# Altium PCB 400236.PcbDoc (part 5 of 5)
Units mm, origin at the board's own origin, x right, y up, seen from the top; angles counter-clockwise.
Board outline 136.53 x 63.5 mm, 4 copper layers (Top Layer, Mid-Layer 1, Mid-Layer 2, Bottom Layer), stack 1.49 mm thick; 344 components, 236 nets, 1364 pads, 1393 vias.
Unrouted connection lines stored in the file: 6.
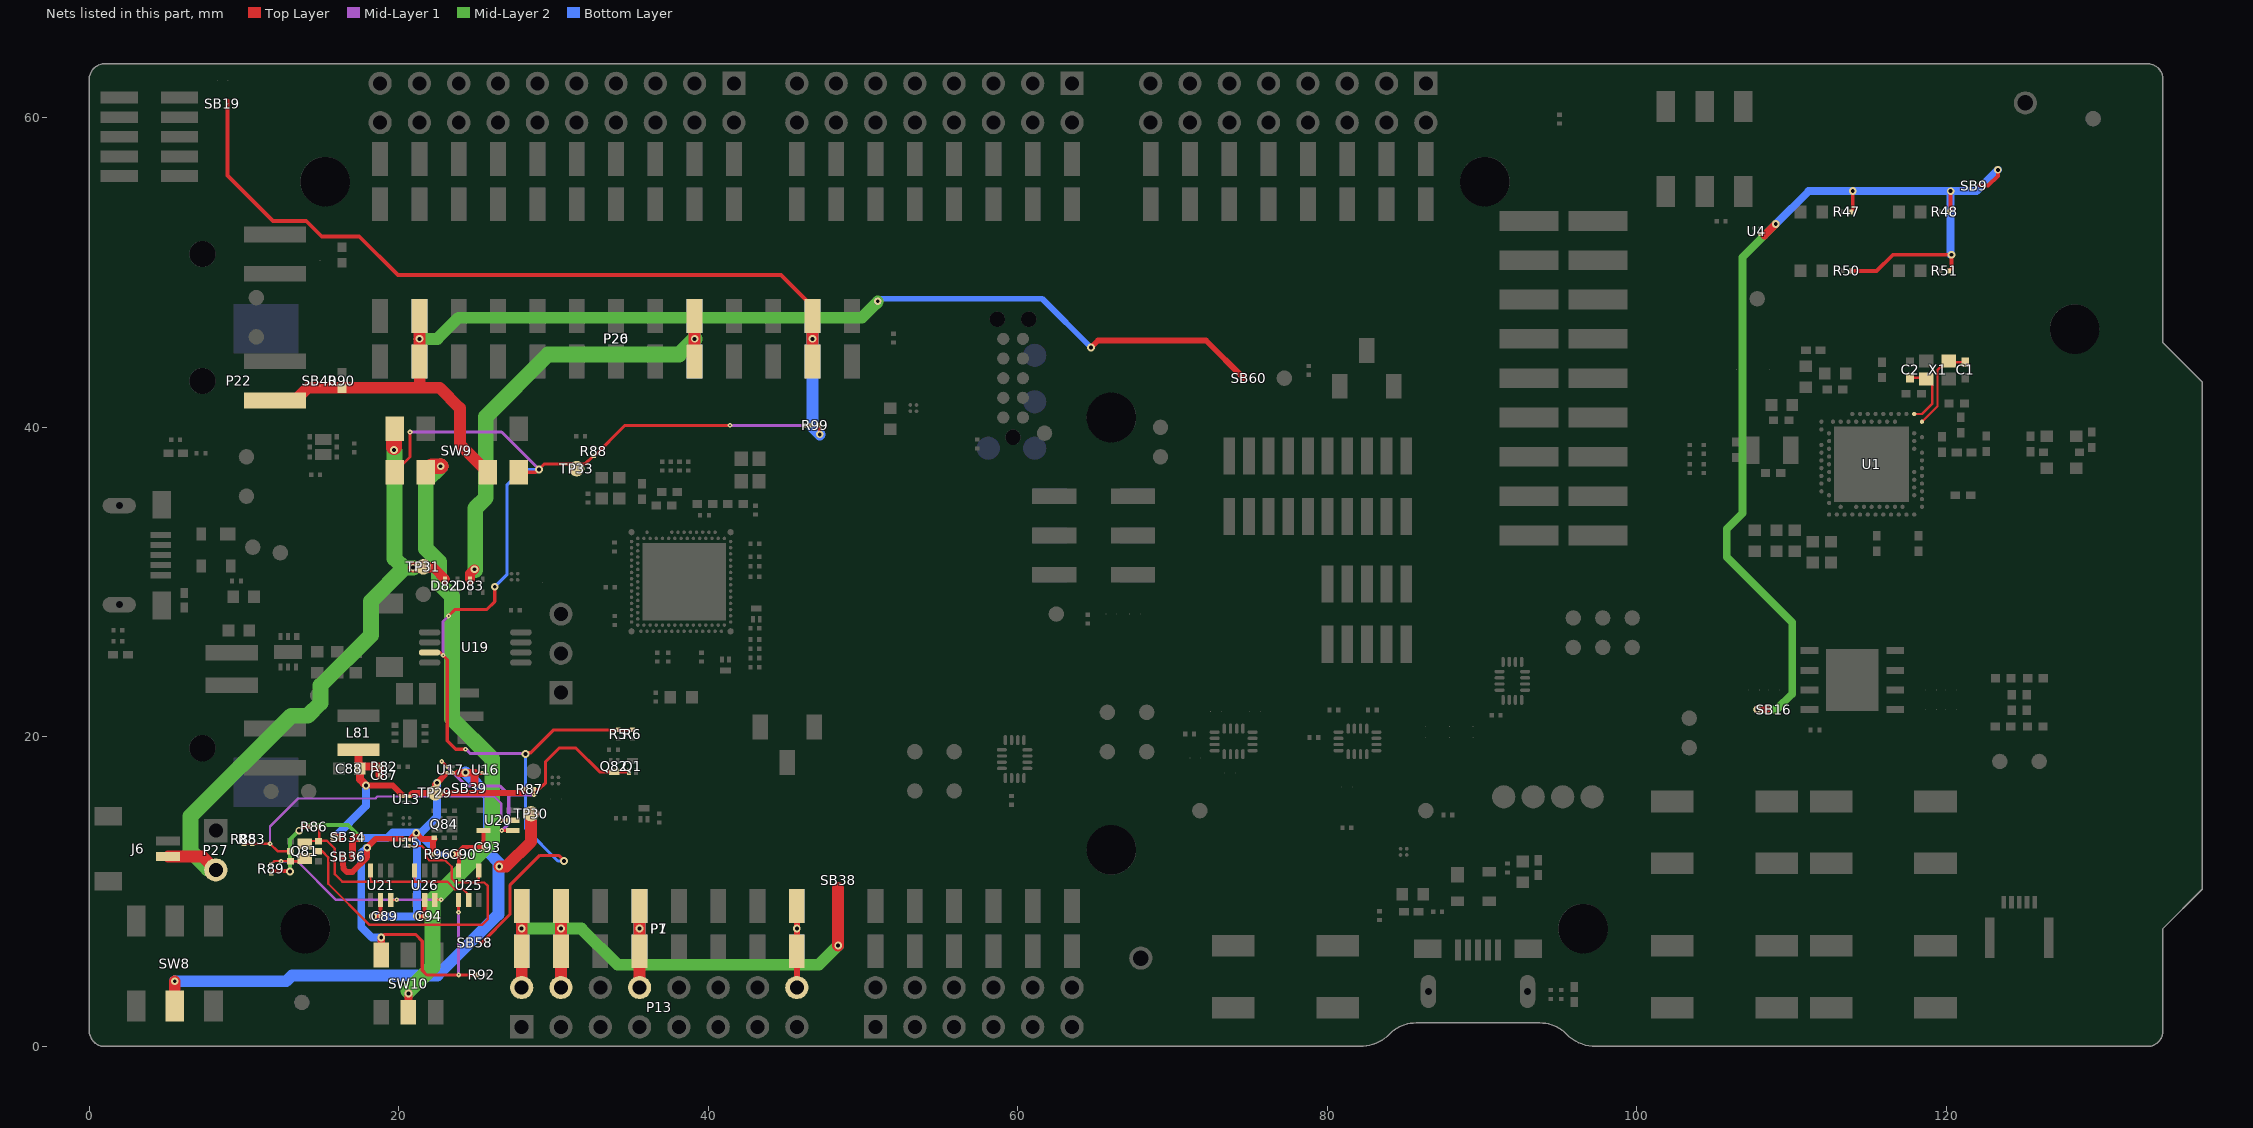
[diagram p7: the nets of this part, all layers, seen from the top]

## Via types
v1: diameter 0.5, hole 0.25, Top Layer to Bottom Layer, tented both sides, 1166 vias
v2: diameter 0.3, hole 0.1, Top Layer to Mid-Layer 1, tented top, 227 vias

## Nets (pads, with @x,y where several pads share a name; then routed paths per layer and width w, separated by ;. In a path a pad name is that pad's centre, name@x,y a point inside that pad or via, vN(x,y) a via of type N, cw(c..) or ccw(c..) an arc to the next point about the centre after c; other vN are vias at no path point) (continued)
VDD_NRF': P20.2 P22.2 P26.2 R90.1 SB40.2 SB60.2 SW9.3 | length 85.3
  Top Layer w0.381: v1(64.719,45.161) 65.176,45.618 72.154,45.618 SB60.2@74.592,43.18
  Top Layer w0.508: P20.2@21.336,44.255 v1(21.336,45.72) P20.2@21.336,47.185
  Top Layer w0.762: P22.2@11.811,41.73 13.284,41.73 14.115,42.561 21.361,42.561 ; P20.2@21.336,47.185 v1(21.336,45.72) P20.2@21.336,44.255 21.361,44.23 21.361,42.561 ; SW9.3@25.749,37.106 23.952,38.903 23.952,41.25 22.641,42.561 21.361,42.561
  Mid-Layer 2 w0.762: v1(21.336,45.72) 22.495,45.72 23.856,47.081 24.748,47.081 49.926,47.081 50.891,48.046 50.891,48.058 50.95,48.118 v1(50.95,48.15)
  Bottom Layer w0.381: v1(50.95,48.15) 50.982,48.15 51.143,48.311 61.57,48.311 v1(64.719,45.161)
  Bottom Layer w0.508: P26.2@21.336,44.255 v1(21.336,45.72) P26.2@21.336,47.185
VDD_NRF_SENSE: R5.1 R6.2 R88.1 R99.1 SB58.1 SW9.1 SW9.4 TP33.1 U19.3 | length 85.6
  Top Layer w0.203: SW9.1@19.749,37.106 20.726,38.084 v2(20.726,39.7) ; U19.3@21.993,25.456 22.677,25.456 v2(22.86,25.273) 23.129,25.004 23.129,19.747 23.673,19.202 v2(24.311,19.202) ; v2(23.216,27.813) 23.647,28.245 25.705,28.245 26.2,28.74 v1(26.2,29.705) ; SB58.1@25.255,6.706 25.356,6.706 27.178,8.528 27.178,10.408 29.117,12.347 30.325,12.347 v1(30.683,11.989) ; SW9.4@27.749,37.106 28.877,37.106 v1(29.058,37.287) 29.413,37.643 32.06,37.643 32.54,38.122 32.54,38.137 32.573,38.171 R88.1@32.588,38.171 ; v1(28.194,18.898) 28.272,18.975 28.525,18.975 30.01,20.46 R5.1@34.175,20.46 R6.2@35.1,20.46 ; R88.1@32.619,38.137 34.613,40.132 v2(41.402,40.132) ; v2(46.25,40.15) R99.1@46.615,40.15
  Mid-Layer 1 w0.203: v2(20.726,39.7) 26.645,39.7 v1(29.058,37.287) ; v2(22.86,25.273) 22.86,27.457 v2(23.216,27.813) ; v2(24.311,19.202) 24.351,19.202 24.634,18.919 28.173,18.919 v1(28.194,18.898) ; v2(41.402,40.132) 46.232,40.132 v2(46.25,40.15)
  Bottom Layer w0.203: v1(26.2,29.705) 27,30.505 27,36.297 27.991,37.287 v1(29.058,37.287) ; v1(28.194,18.898) 28.194,14.078 30.283,11.989 v1(30.683,11.989)
VDD_PER: R47.2 R48.2 R50.2 R51.2 SB9.2 SB16.1 U4.A1 | length 71.5
  Top Layer w0.25: U4.A1@107.95,52.476 108.235,52.476
  Top Layer w0.254: R50.2@113.844,50.107 115.487,50.107 116.535,51.156 v1(120.316,51.156) 120.316,50.269 120.169,50.122 R51.2@120.169,50.107 ; R47.2@113.844,53.917 113.844,53.932 113.94,54.028 v1(113.94,55.271) 113.94,54.443 ; R48.2@120.169,53.917 120.169,53.932 120.265,54.028 v1(120.265,55.264) ; 122.114,55.619 122.289,55.619 122.684,55.619 123.317,56.252 v1(123.317,56.642)
  Top Layer w0.381: v1(107.772,21.768) SB16.1@108.501,21.768
  Top Layer w0.508: 108.229,52.4 v1(108.966,53.137)
  Mid-Layer 2 w0.508: v1(107.772,21.768) 109.017,21.768 110.033,22.784 110.033,27.395 105.804,31.623 105.804,33.44 106.819,34.455 106.819,50.99 v1(108.966,53.137)
  Bottom Layer w0.508: v1(108.966,53.137) 111.093,55.264 v1(120.265,55.264) ; v1@120.265,51.156 v1(120.265,55.264) ; v1(123.317,56.642) 121.939,55.264 v1(120.265,55.264)
VEXT: R92.1 SB36.2 SW10.3 U15.A1 U25.1 | length 27.6
  Top Layer w0.203: v1(18.872,7.036) 19.078,7.241 21.08,7.241 21.514,6.807 21.514,4.928 21.819,4.623 v2(23.876,4.623) R92.1@25.064,4.623 ; SW10.3@18.875,5.914 SW10.3@18.875,6.251 ; v2(23.861,8.676) U25.1@23.861,9.464
  Top Layer w0.381: 16.397,12.265 16.397,11.912 16.402,11.832 16.403,11.824 16.425,11.493 16.643,11.275 17,11.275 17.958,12.233 17.958,12.878 18.504,13.424 U15.A1@20.231,13.424
  Top Layer w0.508: v1(18.872,7.036) 18.872,5.917 SW10.3@18.875,5.914
  Mid-Layer 1 w0.203: v2(23.861,8.676) 23.861,4.638 v2(23.876,4.623)
  Bottom Layer w0.508: v1(17.958,12.842) 17.922,12.842 17.577,12.497 17.577,7.722 18.263,7.036 v1(18.872,7.036)
VEXT_EN: Q81.5 U15.B2 U25.4 | length 23.7
  Top Layer w0.152: Q81.5@14.864,12.624 15.037,12.624 15.443,12.217 15.443,10.516 18.085,7.874 25.4,7.874 25.756,8.23 25.756,10.363 25.527,10.592 25.171,10.592 ; U15.B2@20.698,12.957 21.485,12.957 21.793,12.649 21.793,12.217 21.971,12.039 22.988,12.039 23.419,11.608 23.419,10.846 23.673,10.592 25.171,10.592 ; U25.4@25.161,11.364 25.161,10.602 25.171,10.592
VEXT_EN_INV: Q81.3 R89.2 U21.6 U26.6 | length 14.6
  Top Layer w0.152: R89.2@11.76,11.766 11.775,11.766 11.834,11.825 11.834,11.84 11.975,11.981 12.962,11.981 Q81.3@12.969,11.974 ; Q81.3@12.974,11.974 13.744,11.974 Q81.3@13.919,12.149 ; Q81.3@13.955,11.974 Q81.3@13.995,12.014 ; U21.6@19.471,9.464 19.853,9.464 v2(19.863,9.474) ; U26.6@22.316,9.464 22.326,9.474 v2(22.733,9.474)
  Mid-Layer 1 w0.152: v2(12.395,11.963) 13.462,11.963 15.951,9.474 v2(19.863,9.474) v2(22.733,9.474)
VIN: P1.8 P7.8 P13.16 | length 8.2
  Top Layer w0.381: P13.16@45.72,3.81 P1.8@45.72,6.155 v1(45.72,7.62) P1.8@45.72,9.085
  Bottom Layer w0.381: P7.8@45.72,6.155 v1(45.72,7.62) P7.8@45.72,9.085
VIN3-5V: D83.2 P20.9 P26.9 | length 32.4
  Top Layer w0.635: D83.2@24.613,30.186 24.613,30.556 v1(24.892,30.836)
  Top Layer w0.762: P20.9@39.116,44.255 v1(39.116,45.72) P20.9@39.116,47.185
  Mid-Layer 2 w1.016: v1@24.943,30.785 24.943,34.773 25.629,35.458 25.629,40.691 29.642,44.704 38.1,44.704 v1@39.111,45.714
  Bottom Layer w0.762: P26.9@39.116,44.255 v1(39.116,45.72) P26.9@39.116,47.185
VIO: P1.1 P1.2 P1.4 P7.1 P7.2 P7.4 P13.2 P13.4 P13.8 SB38.1 | length 54.1
  Top Layer w0.381: v1(35.56,7.62) P1.4@35.56,9.085
  Top Layer w0.762: P13.2@27.94,3.81 P1.1@27.94,6.155 P1.1@27.94,9.085 ; P13.4@30.48,3.81 v1(30.48,7.62) P1.2@30.48,9.085 ; P13.8@35.56,3.81 P1.4@35.56,9.085 ; v1(48.387,6.528) 48.387,10.236
  Mid-Layer 2 w0.762: v1(27.94,7.62) v1(30.48,7.62) 31.801,7.62 34.138,5.283 35.535,5.283 ; v1(35.56,7.62) 35.56,5.309 35.535,5.283 ; v1(48.387,6.528) 47.142,5.283 35.535,5.283
  Bottom Layer w0.762: P7.1@27.94,6.155 P7.1@27.94,9.085 ; P7.2@30.48,6.155 P7.2@30.48,9.085 ; P7.4@35.56,6.155 P7.4@35.56,9.085
VIO_REF: P20.12 P26.12 R99.2 SB19.2 | length 58.2
  Top Layer w0.2: R99.2@47.185,40.15 47.185,39.565 v1(47.2,39.55)
  Top Layer w0.25: 8.923,61.138 8.923,56.279 11.877,53.325 14.023,53.325 15.024,52.324 17.45,52.324 19.939,49.835 44.704,49.835 46.736,47.803 P20.12@46.736,47.185
  Top Layer w0.762: P20.12@46.736,44.255 v1(46.736,45.72) P20.12@46.736,47.185
  Bottom Layer w0.762: P26.12@46.736,47.185 v1(46.736,45.72) P26.12@46.736,44.255 46.736,40.014 v1(47.2,39.55)
VLI-ION: D82.2 J6.2 P27.2 SW9.5 TP31.1 | length 42.2
  Top Layer w0.635: v1(20.93,30.937) 22.235,30.937 D82.2@22.987,30.186
  Top Layer w0.762: J6.2@5.105,12.276 7.307,12.276 P27.2@8.179,11.405
  Top Layer w1.016: v1@19.685,38.735 19.685,39.842 SW9.5@19.749,39.906
  Mid-Layer 2 w1.016: P27.2@8.179,11.405 8.086,11.497 7.68,11.497 6.55,12.627 6.55,14.875 13.05,21.375 14.125,21.375 14.95,22.2 14.95,23.325 18.2,26.575 18.2,28.775 20.362,30.937 ; v1@19.725,38.492 19.725,31.532 20.32,30.937 20.362,30.937 ; v1(20.93,30.937) 20.362,30.937
  other v1: 19.685,38.532
VREG: C87.2 C88.2 L81.2 R82.2 SB34.2 U13.A1 | length 11.5
  Top Layer w0.381: v1(17.882,16.866) 19.609,16.866 U13.A1@20.231,16.243
  Top Layer w0.508: v1(15.843,13.509) 16.222,13.509 16.223,13.508 ; L81.2@17.399,19.093 17.399,18.049 C88.2@17.49,17.958 ; v1(17.882,16.866) 17.49,17.257 C88.2@17.49,17.958 ; C87.2@18.79,17.526 18.765,17.551 R82.2@18.765,18.085 17.617,18.085 C88.2@17.49,17.958
  Bottom Layer w0.508: v1(15.843,13.509) 17.882,15.548 v1(17.882,16.866)
VREG_EN: Q81.2 R83.2 R85.1 U20.2 | length 22
  Top Layer w0.152: R85.1@10.004,13.101 R83.2@10.538,13.101 v2(11.684,13.101) 12.161,12.624 Q81.2@12.969,12.624 ; v2(26.619,14.605) U20.2@27.366,14.605
  Mid-Layer 1 w0.152: v2(11.684,13.101) 11.684,14.209 13.499,16.024 18.489,16.024 18.615,16.15 26.166,16.15 26.619,15.697 v2(26.619,14.605)
VREG_EN_INV: Q81.6 R86.2 U21.3 U25.2 U26.3 | length 15.4
  Top Layer w0.152: Q81.6@13.919,13.099 14.094,13.274 Q81.6@14.864,13.274 ; R86.2@14.851,14.2 14.851,13.292 15.359,13.292 15.875,12.776 15.875,11.125 16.358,10.643 18.171,10.643 ; U21.3@18.171,11.364 18.171,10.643 ; U26.3@21.016,11.364 21.016,10.643 ; U25.2@24.511,9.804 24.155,10.16 23.622,10.16 23.139,10.643 21.016,10.643 ; 18.171,10.643 21.016,10.643
VSENSE_SW_OUT: SB39.1 SW8.2 TP30.1 U16.A2 U17.A1 | length 41.3
  Top Layer w0.25: U17.A1@23.517,17.682 23.876,17.682 ; 24.953,17.664 25.36,17.664 U16.A2@25.378,17.682
  Top Layer w0.508: 23.876,17.682 24.308,17.682 24.311,17.684 24.933,17.684 24.971,17.646 24.892,17.566 24.892,17
  Top Layer w0.762: SW8.2@5.528,2.609 v1(5.528,4.216) ; v1(26.492,11.633) 26.949,11.633 28.55,13.233 TP30.1@28.55,14.859
  Bottom Layer w0.762: v1(5.528,4.216) 12.727,4.216 13.106,4.596 22.503,4.596 26.441,8.534 26.441,11.909 25.829,12.521 25.829,16.182 v1(24.308,17.704)
VSRC_NRF: SW9.2 SW10.5 | length 40.6
  Top Layer w0.508: SW10.5@20.625,2.214 v1(20.625,3.429)
  Top Layer w1.016: SW9.2@21.749,37.106 22.133,37.49 v1(22.708,37.49)
  Mid-Layer 2 w1.016: v1@20.625,3.607 22.174,5.156 22.174,9.449 26.035,13.31 26.035,18.593 23.444,21.184 23.444,29.083 22.606,29.921 22.606,31.32 21.749,32.177 21.749,36.532 v1(22.708,37.49)
VSUPPLY: C89.2 C90.2 C93.2 C94.2 Q84.4 R86.1 R87.1 R89.1 R96.1 SB34.1 SB36.1 SB39.2 TP29.1 U13.A2 U15.A2 U17.A2 U20.5 U21.5 U25.5 U26.5 | length 48.9
  Top Layer w0.254: R89.1@11.76,11.196 11.775,11.196 11.908,11.328 v1@12.979,11.328 ; v1(13.564,13.945) 13.571,13.945 13.826,14.2 R86.1@14.265,14.2 ; v1(18.339,8.407) C89.2@18.816,8.407 18.816,9.458 U21.5@18.821,9.464 ; v1(21.184,8.407) C94.2@21.661,8.407 21.661,9.458 U26.5@21.666,9.464 ; U25.5@23.861,11.364 23.896,11.399 C90.2@23.896,12.421 23.896,12.62 24.154,12.878 C93.2@25.471,12.878 25.471,13.95 U20.5@25.466,13.955
  Top Layer w0.381: U15.A2@20.764,13.424 v1(21.128,13.787) 21.504,13.411 22.301,13.411 22.219,13.329 R96.1@22.219,12.471 ; U13.A2@20.777,16.256 20.912,16.391 22.352,16.391 22.352,16.916 v1(22.479,17.043) U17.A2@23.038,17.602 ; TP29.1@22.352,16.383 22.352,16.386 24.201,16.386 24.922,16.386 27.937,16.386 R87.1@28.163,16.612 ; v1(23.444,12.421) C90.2@23.896,12.421
  Top Layer w0.457: 17.022,12.265 17.022,12.618 17.022,13.182 17.022,13.184
  Top Layer w0.508: 17.085,13.469 17.191,13.469 17.544,13.469 v1(17.55,13.475)
  Mid-Layer 2 w0.254: v1(12.979,11.303) 12.979,13.36 v1(13.564,13.945) 13.919,14.3 16.725,14.3 v1(17.55,13.475)
  Bottom Layer w0.381: v1@21.295,13.675 22.55,12.421 v1(23.444,12.421)
  Bottom Layer w0.508: v1(17.55,13.475) 19.257,13.475 19.625,13.843 v1@21.128,13.843 ; v1(18.339,8.407) v1(21.184,8.407) 21.184,13.787 v1@21.128,13.843 ; v1(22.479,17.043) 22.479,14.859 21.463,13.843 v1@21.128,13.843
VSUPPLY_EN: Q1.1 Q82.3 R87.2 U17.B2 U20.1 | length 19.6
  Top Layer w0.152: v2(22.784,18.415) U17.B2@23.117,18.082
  Top Layer w0.203: v2(26.66,13.955) U20.1@27.366,13.955 ; v2(28.733,16.262) R87.2@28.733,16.612 29.058,16.612 29.489,17.043 29.489,18.415 30.362,19.288 31.437,19.288 32.975,17.75 Q82.3@33.925,17.75 Q1.1@34.875,17.75
  Mid-Layer 1 w0.203: v2(22.784,18.415) 24.359,16.84 26.518,16.84 27.096,16.262 ; v2(26.66,13.955) 27.102,14.397 27.102,16.256 27.096,16.262 ; v2(28.733,16.262) 27.096,16.262
XC1: C1.1 U1.B24 X1.1 | length 5.8
  Top Layer w0.152: U1.B24@118.414,40.367 119.414,41.367 119.414,43.717 119.909,44.213 C1.1@121.203,44.213
XC2: C2.1 U1.A23 X1.3 | length 4.3
  Top Layer w0.152: C2.1@117.647,43.213 118.625,43.213 X1.3@118.7,43.138 119.089,42.749 119.089,41.538 118.418,40.867 U1.A23@117.914,40.867
pads on no net: Fid1.0 Fid2.0 J2.4 J2.6@1.944,28.55 J2.6@1.944,34.95 J3.4 J3.6@86.529,3.557 J3.6@92.929,3.557 J4.0 J4.6 J4.7 J4.8 J4.9 J5.0 J5.1 J5.3 J5.5 J6.0 P18.7 P18.8 P19.7 P19.8 P19.9 P21.0 P22.0 P23.0 P25.7 P25.8 P25.11 P25.13 SW8.1 U2. U2.A1 U2.A17 U2.A21 U2.A31 U2.AB2 U2.AD2 U2.AE1 U2.AE31 U2.AF2 U2.AG31 U2.AH2 U2.AJ1 U2.AK2 U2.AK4 U2.AK6 U2.AK8 U2.AK10 U2.AK12 U2.AK14 U2.AK16 U2.AK18 U2.AK20 U2.AL1 U2.AL13 U2.AL15 U2.AL21 U2.AL23 U2.AL31 U2.B10 U2.B14 U2.D2 U2.F2 U2.J1 U2.K2 U2.M2 U2.P2 U2.R31 U2.T2 U2.V2 U2.Y2 U5.1 U5.9 U5.13 U6.1 U6.5 U6.9 U6.13 U7.7 U7.11 U8.11 U8.12 U8.13

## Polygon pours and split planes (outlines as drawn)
VDD on Mid-Layer 2 "Mid_Layer_2-VDD" (solid, remove dead copper, pour order 10): -3.81,-3.81 -3.81,68.58 138.43,68.58 138.43,-3.81
VDD_IMCU on Mid-Layer 2 "Mid_Layer_2-VDD_IMCU" (solid, remove dead copper, pour order 8): 33.025,35.987 33.025,25.093 43.937,25.093 43.937,35.987
GND on Bottom Layer "Bottom_Layer-GND" (solid, remove dead copper, pour order 6): -3.81,-3.81 -3.81,68.58 138.43,68.58 138.43,-3.81
GND on Mid-Layer 1 "Mid_Layer_1-GND" (solid, remove dead copper, pour order 7): -3.81,-3.81 -3.81,68.58 138.43,68.58 138.43,-3.81
GND on Top Layer "Top_Layer-GND" (solid, remove dead copper, pour order 12): -3.81,-3.81 -3.81,68.58 138.43,68.58 138.43,-3.81

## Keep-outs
Top Layer:
  lines w0.152: 90.89,53.591 cw(c90.17,55.88) 91.893,54.209
Mid-Layer 1:
  circle w0.152: c90.17,55.88 r2.4
Mid-Layer 2:
  circle w0.152: c90.17,55.88 r2.4
Bottom Layer:
  circle w0.152: c90.17,55.88 r2.4
Keep-Out Layer:
  circle w0.152: c13.97,7.62 r2.4
  circle w0.152: c66.04,12.7 r2.4
  circle w0.152: c128.27,46.355 r2.4
  circle w0.152: c15.24,55.88 r2.4
  circle w0.152: c66.04,40.64 r2.4
  circle w0.152: c96.52,7.62 r2.4
  circle w0.1: c13.967,0 r0.3
  circle w0.1: c15.067,0 r0.3
  circle w0.1: c16.167,0 r0.3
  circle w0.1: c123.987,0 r0.3
  circle w0.1: c122.887,0 r0.3
  circle w0.1: c121.787,0 r0.3
  circle w0.1: c136.526,42.025 r0.3
  circle w0.1: c136.526,40.926 r0.3
  circle w0.1: c136.526,39.826 r0.3
  circle w0.1: c121.787,63.5 r0.3
  circle w0.1: c122.887,63.5 r0.3
  circle w0.1: c123.987,63.5 r0.3
  circle w0.1: c13.967,63.5 r0.3
  circle w0.1: c15.067,63.5 r0.3
  circle w0.1: c16.167,63.5 r0.3
  circle w0.1: c0,48.692 r0.3
  circle w0.1: c0,49.792 r0.3
  circle w0.1: c0,50.891 r0.3
  circle w0.1: c0,17.705 r0.3
  circle w0.1: c0,18.804 r0.3
  circle w0.1: c0,19.904 r0.3

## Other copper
Top Layer:
  rectangle net V5V: 13.231,24.103 13.866,24.738
  rectangle net ANT: 134.92,20.343 136.19,21.105
  pour cut-out: 17.625,25.8 18.65,25.8 18.775,25.675 18.775,25 18.375,24.6 17.725,24.6 17.625,24.7 17.625,24.875
  pour cut-out: 90.658,5.004 90.658,7.315 96.62,7.315 96.62,5.004
  pour cut-out: 91.161,32.131 91.161,33.401 89.891,33.401 89.891,32.131
  pour cut-out: 107.164,32.217 107.164,33.617 110.834,33.617 110.834,32.217
  pour cut-out: 110.664,31.367 110.664,32.867 113.164,32.867 113.164,31.367
  pour cut-out: 115.414,36.867 115.414,38.367 117.914,38.367 117.914,36.867
  pour cut-out: 117.737,33.63 116.676,34.691 118.444,36.458 119.505,35.398
  pour cut-out: 60.528,30.937 68.073,30.937 68.071,32.715 60.528,32.715
  pour cut-out: 129.92,-1.27 136.786,-1.27 136.748,45.415 129.925,45.415
  pour cut-out: -0.229,28.204 2.824,28.204 2.818,35.281 -0.228,35.281
  pour cut-out: 28.981,25.603 28.981,26.873 27.711,26.873 27.711,25.603
  pour cut-out: 118.567,26.975 117.297,26.975 117.297,25.705 118.567,25.705
  pour cut-out: 11.252,51.765 9.982,51.765 9.982,50.495 11.252,50.495
  pour cut-out: 86.385,35.687 85.115,35.687 85.115,34.417 86.385,34.417
  pour cut-out: 60.757,53.086 48.387,53.086 48.387,51.816 60.757,51.816
  pour cut-out: 107.163,43.256 107.163,44.526 105.054,44.526 105.054,43.256
  pour cut-out: 22.149,1.168 22.149,2.438 20.879,2.438 20.879,1.168
  pour cut-out: 20.447,5.715 20.447,6.985 19.177,6.985 19.177,5.715
  pour cut-out: 20.218,1.143 20.218,3.264 18.948,3.264 18.948,1.143
  pour cut-out: 11.252,43.635 9.982,43.635 9.982,42.365 11.252,42.365
  pour cut-out: 118.496,37.293 121.239,37.293 121.239,39.142 120.439,39.142 120.439,40.188 118.496,40.188
Mid-Layer 1:
  pour cut-out: 110.28,27.254 110.28,21.336 106.28,21.336 106.28,27.254
  pour cut-out: 121.71,25.984 121.71,20.066 117.71,20.066 117.71,25.984
  pour cut-out: 49.126,39.244 49.126,41.556 51.5,41.556 51.5,39.244
  pour cut-out: 110.28,18.44 107.467,18.44 107.467,25.333 110.28,25.333
  pour cut-out: 28.315,29.25 28.315,31.318 30.325,31.318 30.325,29.25
  pour cut-out: 92.078,58.763 92.078,61.074 95.377,61.074 95.377,58.763
  pour cut-out: 85.782,11.379 85.782,13.691 88.157,13.691 88.157,11.379
  pour cut-out: 129.92,-1.27 136.786,-1.27 136.748,45.415 129.925,45.415
  pour cut-out: 104.44,46.723 110.357,46.723 110.357,42.723 104.44,42.723
  pour cut-out: 15.45,11.557 15.45,14.529 17.824,14.529 17.824,11.557
  pour cut-out: 23.4,15.494 23.4,17.805 25.774,17.805 25.774,15.494
  pour cut-out: 56.725,19.202 56.725,21.514 59.099,21.514 59.099,19.202
  pour cut-out: 56.598,17.094 56.598,19.406 58.972,19.406 58.972,17.094
  pour cut-out: 60.618,17.843 60.618,20.155 62.992,20.155 62.992,17.843
  pour cut-out: 59.969,14.973 59.969,17.285 62.344,17.285 62.344,14.973
  pour cut-out: 64.878,26.695 64.878,29.007 68.656,29.007 68.656,26.695
  pour cut-out: 120.612,48.831 120.612,57.137 122.987,57.137 122.987,48.831
  pour cut-out: 7.449,59.95 7.449,63.449 9.823,63.449 9.823,59.95
  pour cut-out: 70.263,17.45 70.263,19.761 72.637,19.761 72.637,17.45
  pour cut-out: 71.438,20.587 71.438,22.898 73.812,22.898 73.812,20.587
  pour cut-out: 74.175,20.512 74.175,22.823 76.549,22.823 76.549,20.512
  pour cut-out: 73.369,16.612 73.369,18.923 75.744,18.923 75.744,16.612
  pour cut-out: 28.448,14.884 28.448,17.196 31.747,17.196 31.747,14.884
  pour cut-out: 80.042,13.995 80.042,18.161 82.416,18.161 82.416,13.995
  pour cut-out: 84.979,19.177 84.979,21.488 90.941,21.488 90.941,19.177
  pour cut-out: 13.678,49.898 13.678,52.21 16.053,52.21 16.053,49.898
  pour cut-out: 13.704,41.87 13.704,44.181 16.078,44.181 16.078,41.87
  pour cut-out: 47.232,9.614 47.232,11.925 49.606,11.925 49.606,9.614
  pour cut-out: 23.654,5.486 23.654,7.798 26.028,7.798 26.028,5.486
  pour cut-out: 73.641,41.986 73.641,44.298 76.016,44.298 76.016,41.986
  pour cut-out: 73.667,40.03 73.667,42.342 76.041,42.342 76.041,40.03
  pour cut-out: 131.445,36.392 119.918,36.392 119.918,40.392 131.445,40.392
Mid-Layer 2:
  pour cut-out: 27.742,32.85 26.8,32.85 26.8,32.925 27.75,32.925
  pour cut-out: 129.92,-1.27 136.786,-1.27 136.748,45.415 129.925,45.415
  pour cut-out: 131.445,36.392 119.918,36.392 119.918,40.392 131.445,40.392
Bottom Layer:
  pour cut-out: 129.92,-1.27 136.786,-1.27 136.748,45.415 129.925,45.415

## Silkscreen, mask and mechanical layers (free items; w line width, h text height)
Top Overlay:
  drawing of 85 lines, arcs and shapes, not listed
  text "nRF ONLY" at 97.765,62.052 h1.65
  text "DEFAULT" at 104.877,62.052 h1.65
  text "GND" at 12.225,61.7 h1.8
  text "GND" at 91.389,61.709 h1.8
  text ".PCBNumber" at 116.028,61.468 h2
  text ".PCBRevision" at 116.093,60.165 h1.5
  text "GND" at 123.469,58.471 h1.8
  text "LED1" at 109.622,54.654 h2.03
  text "LED2" at 115.82,54.654 h2.03
  text "Debug out" at 0.406,54.127 h1.78
  text "P0.11" at 87.757,52.781 h1.65
  text "P0.12" at 99.568,52.781 h1.65
  text "LED3" at 109.495,50.869 h2.03
  text "LED4" at 115.845,50.869 h2.03
  text "VDD_HV" at 1.016,50.775 h1.4
  text "P0.13" at 87.757,50.241 h1.65
  text "P0.14" at 99.568,50.241 h1.65
  text "P0.27" at 19.304,49.661 h1.65 r90
  text "P0.26" at 21.844,49.661 h1.65 r90
  text "P0.02" at 24.384,49.661 h1.65 r90
  text "GND" at 26.924,49.661 h1.65 r90
  text "P1.15" at 29.464,49.661 h1.65 r90
  text "P1.14" at 32.004,49.661 h1.65 r90
  text "P1.13" at 34.544,49.661 h1.65 r90
  text "P1.12" at 37.084,49.661 h1.65 r90
  text "P1.11" at 39.624,49.661 h1.65 r90
  text "P1.10" at 42.164,49.661 h1.65 r90
  text "P1.08" at 46.228,49.661 h1.65 r90
  text "P1.07" at 48.768,49.661 h1.65 r90
  text "P1.06" at 51.308,49.661 h1.65 r90
  text "P1.05" at 53.848,49.661 h1.65 r90
  text "P1.04" at 56.388,49.661 h1.65 r90
  text "P1.03" at 58.928,49.661 h1.65 r90
  text "P1.02" at 61.468,49.661 h1.65 r90
  text "P0.10" at 69.088,49.661 h1.65 r90
  text "P0.09" at 71.628,49.661 h1.65 r90
  text "P0.08" at 74.168,49.661 h1.65 r90
  text "P0.07" at 76.708,49.661 h1.65 r90
  text "P0.06" at 79.248,49.661 h1.65 r90
  text "P0.05" at 81.788,49.661 h1.65 r90
  text "P0.01" at 84.328,49.661 h1.65 r90
  text "P0.00" at 86.868,49.661 h1.65 r90
  text "P0.15" at 87.757,47.701 h1.65
  text "P0.16" at 99.568,47.701 h1.65
  text "nRF current" at 0.483,47.193 h1.78
  text "measurement" at 0.483,45.898 h1.78
  text "For evaluation only; / not FCC approved for resale." at 133.655,45.575 h1.52 r90
  text "Alt." at 79.756,45.339 h1.65
  text "Def." at 83.439,45.339 h1.65
  text "P0.17" at 87.757,45.161 h1.65
  text "P0.18" at 99.568,45.161 h1.65
  text "GPIO" at 102.997,44.958 h1.4
  text "XTAL" at 102.997,43.688 h1.4
  text "P0.19" at 87.757,42.621 h1.65
  text "P0.20" at 99.568,42.621 h1.65
  text "VDD" at 1.016,42.57 h1.4
  text "VIO / REF" at 47.705,40.946 h1.14 r90
  text "SWD / SEL" at 24.65,40.775 h1.14 r90
  text "VDD / nRF" at 19.761,40.755 h1.14 r90
  text "VDD / nRF'" at 22.301,40.755 h1.14 r90
  text "SWO" at 31.825,40.65 h1.14 r90
  text "(ARDUINO D0) P1.01" at 64.059,40.552 h1.65 r90
  text "SWD / IO" at 27.508,40.527 h1.14 r90
  text "SWD / CLK" at 30.048,40.527 h1.14 r90
  text "TRACE" at 80.391,40.513 h1.65
  text "RESET" at 34.4,40.35 h1.14 r90
  text "P0.21" at 87.757,40.081 h1.65
  text "P0.22" at 99.568,40.081 h1.65
  text "VIN / 3-5V" at 40.1,39.85 h1.14 r90
  text "VDD / nRF_HV" at 42.625,38.975 h1.14 r90
  text "VDD / nRF_HV'" at 45.161,38.803 h1.14 r90
  text "P0.23" at 87.757,37.541 h1.65
  text "P0.24" at 99.568,37.541 h1.65
  text "IMCU USB" at 0.381,36.195 h2.29
  text "P1.14" at 57.889,35.082 h1.52
  text "5V" at 69.248,35.031 h1.52
  text "P0.25" at 87.757,35.001 h1.65
  text "P1.00" at 99.568,35.001 h1.65
  text "Li-Po   VDD   USB" at 18.313,34.95 h1.65
  text "nRF power source" at 17.12,33.299 h2.03
  text "P1.13" at 69.248,32.567 h1.52
  text "P1.15" at 57.918,32.542 h1.52
  text "P1.09" at 87.757,32.461 h1.65
  text "GND" at 99.568,32.461 h1.65
  text "DETECT" at 69.248,30.024 h1.52
  text "RESET" at 56.955,30.002 h1.52
  text "Debug in" at 79.052,23.3 h2
  text "SB20-22" at 106.934,22.225 h1.52 r90
  text "SB10-12" at 110.465,22.225 h1.52 r90
  text "External / supply" at -1.5,21.925 h1.78
  text "FLOW  / CONTROL" at 41.881,21.589 h1.65
  text "SB13-15" at 118.364,21.463 h1.52 r90
  text "SB23-25" at 121.92,21.463 h1.52 r90
  text "-" at 14.007,19.854 h3
  text "VCOM" at 37.05,18.825 h1.65
  text "BUTTON 1" at 102.594,17.19 h1.78
  text "BUTTON 2" at 112.641,17.19 h1.78
  text "+" at 13.737,17.065 h3
  text "ON" at 42.2,16.625 h1.65
  text "OFF" at 45.9,16.625 h1.65
  text "Li-po" at 2.825,15.425 h1.78
  text "-" at 5.487,13.582 h3
  text "N.C." at 46.253,10.465 h1.65 r90
  text "VDD" at 28.365,10.462 h1.65 r90
  text "VDD" at 30.905,10.462 h1.65 r90
  text "RESET" at 33.445,10.462 h1.65 r90
  text "VDD" at 35.985,10.462 h1.65 r90
  text "5V" at 38.525,10.462 h1.65 r90
  text "GND" at 41.065,10.462 h1.65 r90
  text "GND" at 43.605,10.462 h1.65 r90
  text "P0.03 (A0)" at 51.225,10.462 h1.65 r90
  text "P0.04" at 53.765,10.462 h1.65 r90
  text "P0.28" at 56.305,10.462 h1.65 r90
  text "P0.29" at 58.845,10.462 h1.65 r90
  text "P0.30" at 61.385,10.462 h1.65 r90
  text "P0.31" at 63.925,10.462 h1.65 r90
  text "+" at 5.216,10.332 h3
  text "NFC" at 123.123,9.926 h2.29
  text "BUTTON 4" at 112.691,8.011 h1.78
  text "BUTTON 3" at 102.518,8 h1.78
  text "RESET" at 75.31,7.871 h1.78
  text "nRF52840 USB" at 84.861,7.087 h1.78
  text "VEXT   nRF" at 16.662,6.807 h1.78
  text "GND" at 69.139,5.182 h1.8
  text "Power" at 11.506,3.2 h2.03 r90
  text "GND" at 68.402,0.761 h1.8
  text ".ProductName" at 132.669,0.755 h3 r90
  text "ON" at 2.911,0.229 h1.78
  text "OFF" at 5.655,0.229 h1.78
  text "OFF" at 18.009,0.203 h1.78
  text "ON" at 21.438,0.203 h1.78
Bottom Overlay:
  drawing of 1286 lines, arcs and shapes, not listed
  text "J-Link" at 10.033,62.614 h1.45 r90
  text "www.segger.com" at 11.184,62.532 h1.68 r90
  text "TM" at 9.611,59.144 h0.94 r90
  text "S" at 8.174,58.931 h1.35 r90
  text "E" at 8.174,58.041 h1.35 r90
  text "Technology" at 10.033,57.861 h1.45 r90
  text "G" at 8.174,57.257 h1.35 r90
  text "G" at 8.174,56.266 h1.35 r90
  text "E" at 8.174,55.242 h1.35 r90
  text "R" at 8.174,54.407 h1.35 r90
  text "P0.27" at 19.228,53.111 h1.52 r90
  text "P0.26" at 21.768,53.111 h1.52 r90
  text "P0.02" at 24.308,53.111 h1.52 r90
  text "GND" at 26.849,53.111 h1.52 r90
  text "P1.15" at 29.388,53.111 h1.52 r90
  text "P1.14" at 31.928,53.111 h1.52 r90
  text "P1.13" at 34.468,53.111 h1.52 r90
  text "P1.12" at 37.008,53.111 h1.52 r90
  text "P1.11" at 39.548,53.111 h1.52 r90
  text "P1.10" at 42.088,53.111 h1.52 r90
  text "P1.08" at 46.152,53.111 h1.52 r90
  text "P1.07" at 48.693,53.111 h1.52 r90
  text "P1.06 (D5)" at 51.233,53.111 h1.52 r90
  text "P1.05 (D4)" at 53.773,53.111 h1.52 r90
  text "P1.04 (D3)" at 56.313,53.111 h1.52 r90
  text "P1.03 (D2)" at 58.853,53.111 h1.52 r90
  text "P1.02 (D1)" at 61.393,53.111 h1.52 r90
  text "P1.01 (ARDUINO D0)" at 63.933,53.111 h1.52 r90
  text "P0.10" at 69.038,53.111 h1.52 r90
  text "P0.09" at 71.578,53.111 h1.52 r90
  text "P0.08" at 74.118,53.111 h1.52 r90
  text "P0.07" at 76.658,53.111 h1.52 r90
  text "P0.06" at 79.198,53.111 h1.52 r90
  text "P0.05" at 81.738,53.111 h1.52 r90
  text "P0.01" at 84.278,53.111 h1.52 r90
  text "P0.00" at 86.793,53.111 h1.52 r90
  text "(SCL)" at 20.346,52.07 h1.52 r90
  text "(SDA)" at 22.886,52.07 h1.52 r90
  text "(AREF)" at 25.426,52.07 h1.52 r90
  text "(D13)" at 30.506,52.07 h1.52 r90
  text "(D12)" at 33.046,52.07 h1.52 r90
  text "(D11)" at 35.586,52.07 h1.52 r90
  text "(D10)" at 38.126,52.07 h1.52 r90
  text "(D9)" at 40.666,52.07 h1.52 r90
  text "(D8)" at 43.206,52.07 h1.52 r90
  text "(D7)" at 47.27,52.07 h1.52 r90
  text "(D6)" at 49.81,52.07 h1.52 r90
  text "GPIO" at 76.911,48.701 h1.99 r90
  text "P0.00" at 80.747,48.441 h1.65 r90
  text "P0.01" at 86.131,48.441 h1.65 r90
  text "P0.11" at 90.17,48.441 h1.65 r90
  text "P0.12" at 92.862,48.441 h1.65 r90
  text "P0.24" at 95.555,48.441 h1.65 r90
  text "P0.25" at 98.247,48.441 h1.65 r90
  text "P0.13" at 100.94,48.441 h1.65 r90
  text "P0.14" at 103.632,48.441 h1.65 r90
  text "P0.15" at 106.324,48.441 h1.65 r90
  text "P0.16" at 109.017,48.441 h1.65 r90
  text "P0.17" at 111.713,48.459 h1.65 r90
  text "P0.19" at 114.405,48.459 h1.65 r90
  text "P0.20" at 117.098,48.459 h1.65 r90
  text "P0.21" at 119.79,48.459 h1.65 r90
  text "P0.22" at 122.483,48.459 h1.65 r90
  text "P0.23" at 125.175,48.459 h1.65 r90
  text "Function" at 76.9,42.875 h1.99 r90
  text "Button 1" at 90.12,42.415 h1.65 r90
  text "Button 2" at 92.812,42.415 h1.65 r90
  text "Button 3" at 95.505,42.415 h1.65 r90
  text "Button 4" at 98.197,42.415 h1.65 r90
  text "GPIO" at 27.3,41.775 h1.99 r90
  text "LED 1" at 100.915,41.622 h1.65 r90
  text "LED 2" at 103.607,41.622 h1.65 r90
  text "LED 3" at 106.299,41.622 h1.65 r90
  text "LED 4" at 108.992,41.622 h1.65 r90
  text "P0.05" at 29.82,41.583 h1.65 r90
  text "P0.06" at 32.512,41.583 h1.65 r90
  text "P0.07" at 35.204,41.583 h1.65 r90
  text "P0.08" at 37.897,41.583 h1.65 r90
  text "P0.18" at 40.589,41.583 h1.65 r90
  text "P1.00" at 43.282,41.583 h1.65 r90
  text "P0.09" at 52.222,41.583 h1.65 r90
  text "P0.10" at 56.794,41.583 h1.65 r90
  text "DIO0" at 117.098,41.5 h1.65 r90
  text "DIO1" at 119.79,41.5 h1.65 r90
  text "DIO2" at 122.483,41.5 h1.65 r90
  text "DIO3" at 125.175,41.5 h1.65 r90
  text "CLK" at 114.405,41.319 h1.65 r90
  text "XL2" at 86.131,41.111 h1.65 r90
  text "XL1" at 80.747,41.015 h1.65 r90
  text "CS" at 111.713,40.711 h1.65 r90
  text "SWDCLK" at 48.666,39.218 h1.65 r90
  text "SWDIO" at 45.925,38.7 h1.65 r90
  text "Function" at 27.3,36.025 h1.99 r90
  text "SB13/23" at 111.713,35.248 h1.65 r90
  text "SB11/21" at 114.405,35.248 h1.65 r90
  text "SB12/22" at 117.098,35.248 h1.65 r90
  text "SB14/24" at 119.79,35.248 h1.65 r90
  text "SB15/25" at 122.483,35.248 h1.65 r90
  text "SB10/20" at 125.175,35.248 h1.65 r90
  text "RESET" at 40.513,34.804 h1.65 r90
  text "NFC2" at 56.82,34.816 h1.65 r90
  text "NFC1" at 52.248,34.72 h1.65 r90
  text "SB2" at 79.4,34.671 h1.65 r90
  text "SB4" at 82.093,34.671 h1.65 r90
  text "SB1" at 84.785,34.671 h1.65 r90
  text "SB3" at 87.478,34.671 h1.65 r90
  text "SB5" at 100.94,34.671 h1.65 r90
  text "SB6" at 103.632,34.671 h1.65 r90
  text "SB7" at 106.324,34.671 h1.65 r90
  text "SB8" at 109.017,34.671 h1.65 r90
  text "SWO" at 43.231,34.573 h1.65 r90
  text "TXD" at 32.462,34.249 h1.65 r90
  text "RXD" at 37.846,34.259 h1.65 r90
  text "Short" at 76.911,34.155 h1.99 r90
  text "CTS" at 35.154,34.125 h1.65 r90
  text "RTS" at 29.769,34.044 h1.65 r90
  text "HW" at 27.73,28.448 h1.99 r90
  text "GPIO" at 85.083,27.927 h1.52 r90
  text "GPIO" at 120.015,27.927 h1.52 r90
  text "GPIO" at 34.773,27.813 h1.52 r90
  text "IMCU" at 43.334,27.812 h1.52 r90
  text "GPIO" at 57.93,26.381 h1.52 r90
  text "HW" at 76.911,25.519 h1.99 r90
  text "N.C" at 54.864,25.4 h1.27 r90
  text "SB2x" at 115.443,25.057 h1.27 r90
  text "SB1x" at 117.729,25.057 h1.27 r90
  text "PIN" at 50.883,24.171 h1.52 r90
  text "MEM" at 120.019,23.271 h1.52 r90
  text "VDD" at 101.803,23.126 h1.52 r90
  text "PIN" at 80.574,22.364 h1.52 r90
  text "PIN" at 115.57,22.364 h1.52 r90
  text "0R" at 57.658,22.225 h1.27 r90
  text "IF OFF" at 38.735,21.209 h1.52 r90
  text "NFC" at 53.957,21.224 h1.52 r90
  text "Button 1" at 106.324,18.061 h1.65 r90
  text "Button 2" at 108.9,18.061 h1.65 r90
  text "Function" at 103.775,18.05 h1.99 r90
  text "Function" at 116.916,17.284 h1.52 r90
  text "Default" at 124.474,17.183 h1.52 r90
  text "CTS" at 111.709,16.429 h1.65 r90
  text "P0.03 (A0)" at 51.181,16.393 h1.52 r90
  text "P0.30 (A4)" at 61.335,16.35 h1.52 r90
  text "P0.28 (A2)" at 56.261,16.229 h1.52 r90
  text "P0.29 (A3)" at 58.801,16.215 h1.52 r90
  text "P0.04 (A1)" at 53.721,16.083 h1.52 r90
  text "P0.31 (A5)" at 63.881,15.969 h1.52 r90
  text "RESET" at 33.447,13.808 h1.52 r90
  text "GND" at 41.067,13.139 h1.52 r90
  text "GND" at 43.53,13.139 h1.52 r90
  text "VDD" at 28.373,12.977 h1.52 r90
  text "VDD" at 30.913,12.977 h1.52 r90
  text "VDD" at 35.993,12.977 h1.52 r90
  text "N.C." at 46.197,12.665 h1.52 r90
  text "5V" at 38.558,11.889 h1.52 r90
  text "HW" at 114.249,11.676 h1.99 r90
  text "P0.11" at 106.224,10.079 h1.65 r90
  text "P0.12" at 108.917,10.079 h1.65 r90
  text "P0.07" at 111.609,10.079 h1.65 r90
  text "Def." at 103.835,9.957 h1.99 r90
  text "Alternative" at 124.46,9.055 h1.52 r90
  text "Pb" at 10.019,9.036 h3.05 r90
  text "TRACE / SW" at 121.234,8.648 h1.52 r90
  text "P1.07" at 106.224,5.301 h1.65 r90
  text "P1.08" at 108.917,5.301 h1.65 r90
  text "P0.04" at 111.609,5.301 h1.65 r90
  text "Alt." at 103.835,4.691 h1.99 r90
Board Outline:
  the board outline again, w0.254
Top Assembly:
  drawing of 47 lines, arcs and shapes, not listed
Bottom Assembly:
  drawing of 47 lines, arcs and shapes, not listed
Top Impedance:
  lines w0.138: 4.619,31.75 6.34,31.75 cw(c6.34,31.242) 6.699,31.601 7.244,31.055 7.244,31.062 7.754,31.571 ; 4.619,32.398 6.34,32.398 ccw(c6.34,32.906) 6.699,32.546 7.234,33.082 ; 7.244,33.099 7.248,33.095 7.754,32.59 ccw(c8.552,33.388) 8.552,32.259 11.506,32.259 ccw(c11.506,32.571) 11.727,32.35 11.811,32.434 cw(c12.344,31.901) 12.344,32.655 cw(c12.344,31.897) 12.88,32.433 12.964,32.349 ccw(c13.183,32.568) 13.163,32.259 ccw(c13.153,32.935) 13.631,32.457 14.84,33.666 ; 14.837,33.669 cw(c16.073,32.433) 16.063,34.181 ; 35.439,32.827 35.439,33.303 ; 35.839,32.827 35.839,32.877 35.714,33.002 35.714,33.379 ; 89.086,5.985 89.086,8.495 ccw(c88.578,8.495) 88.938,8.855 88.402,9.39 88.912,9.899 ccw(c88.114,10.697) 89.242,10.697 89.242,12.23 cw(c91.338,12.23) 91.338,14.326 ccw(c91.338,16.411) 92.813,14.936 94.183,16.307 ; 89.734,5.983 89.734,8.495 cw(c90.242,8.495) 89.883,8.855 ; 89.883,8.854 90.429,9.4 ; 90.44,9.39 89.931,9.899 cw(c90.729,10.697) 89.6,10.697 89.6,12.232 cw(c91.338,12.232) 91.338,13.97 ccw(c91.338,16.418) 93.069,14.687 93.522,15.139 ccw(c93.294,16.129) 94.284,15.901 ; 94.204,16.333 cw(c95.199,16.129) 94.995,17.124 ; 94.284,15.902 106.34,27.958 cw(c108.136,26.162) 108.136,28.702 113.295,28.702 ; 94.998,17.121 106.088,28.211 cw(c108.136,26.162) 108.136,29.06 113.295,29.06 ccw(c113.295,29.693) 113.928,29.693 113.928,32.467 ccw(c113.29,32.467) 113.741,32.918 113.244,33.415 cw(c113.89,34.061) 112.977,34.061 ; 112.914,34.367 112.982,34.299 112.982,34.061 ; 113.295,28.702 ccw(c113.295,29.693) 114.286,29.693 114.286,32.467 ccw(c113.29,32.467) 113.994,33.172 113.498,33.669 cw(c113.89,34.061) 113.335,34.061 113.335,34.289 113.414,34.367 ; 7.754,31.571 cw(c8.551,30.773) 8.551,31.901 ; 7.754,31.571 cw(c8.551,30.773) 8.551,31.901 ; 8.551,31.901 9.728,31.901 cw(c9.728,31.592) 9.947,31.811 10.031,31.727 ccw(c10.566,32.263) 10.566,31.505 ccw(c10.566,32.259) 11.1,31.726 11.184,31.81 cw(c11.405,31.589) 11.405,31.901 13.147,31.901 ccw(c13.147,32.944) 13.884,32.207 15.102,33.425 15.107,33.43 ; 15.107,33.43 cw(c16.063,32.464) 15.112,33.435 cw(c16.063,32.464) 16.063,33.823 34.737,33.823 cw(c34.737,33.062) 35.275,33.6 35.276,33.6 35.344,33.532 ; 15.107,33.43 15.107,33.43 ; 16.063,34.181 cw(c16.073,32.433) 16.073,34.181 ; 16.063,34.181 16.073,34.181 ; 16.073,34.181 34.737,34.181 ; 34.737,34.181 cw(c34.737,33.081) 35.515,33.859 cw(c35.035,33.379) 35.714,33.379 ; 34.737,34.181 34.737,34.181 ; 35.344,33.532 cw(c35.115,33.303) 35.439,33.303 ; 35.344,33.532 ccw(c35.115,33.303) 35.344,33.532 ; 35.344,33.532 35.344,33.532 ; 35.439,33.303 35.439,33.303 ; 35.714,33.379 35.714,33.379
  lines w0.871: 121.681,38.379 126.25,38.379
  text "50ohm impedance" at 115.824,39.37 h2
  text "90ohm differensial impedance" at 7.417,35.382 h2
  text "90ohm differensial impedance" at 90.119,14.402 h2 r45
Top Via Capping (Mech16):
  text "All 0.250mm through holes: IPC-4761 Type VII" at 36.75,34.975 h2
  text "All blind holes filled with copper" at 36.75,32.4 h2

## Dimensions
132.969,62.484 to 136.175,65.69 on Dimensions
0,1.016 to 90.17,55.88 on Dimensions
0,1.016 to 133.985,1.016 on Dimensions
0,1.016 to 136.525,10.16 on Dimensions
0,1.016 to 13.97,7.62 on Dimensions
0,1.016 to 15.24,55.88 on Dimensions
0,1.016 to 66.04,12.7 on Dimensions
0,1.016 to 96.52,7.62 on Dimensions
132.969,0 to 132.969,63.5 on Dimensions
132.969,0 to 96.52,7.62 on Dimensions
132.969,0 to 66.04,12.7 on Dimensions
132.969,0 to 66.04,40.64 on Dimensions
132.969,0 to 15.24,55.88 on Dimensions
132.969,0 to 128.27,46.355 on Dimensions
0,1.016 to 128.27,46.355 on Dimensions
